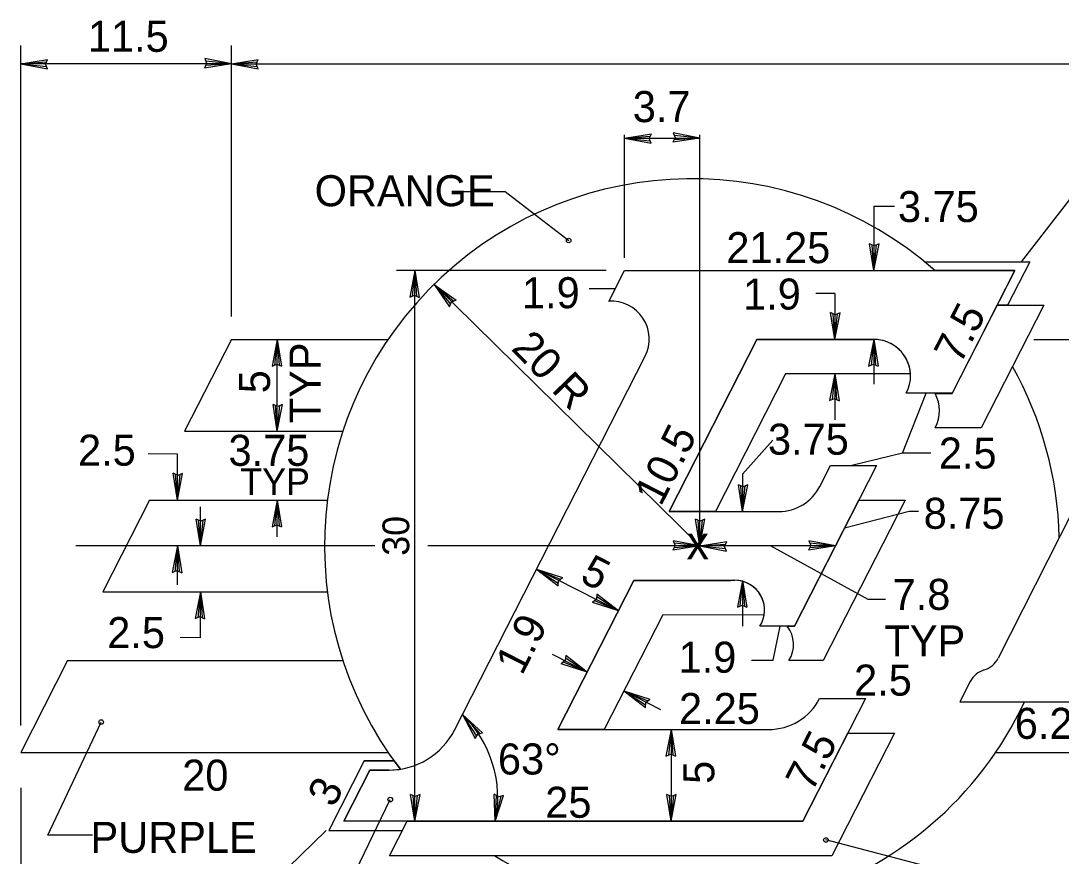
# Model space of a CAD drawing. Extents: x 10268197 to 10268739, y 2141503 to 2142677.
# Drawn here: x 10268676.64 to 10268700.09, y 2142405.46 to 2142424.3 of the extents above; entities that cross this region are included whole.
import ezdxf

# ---------------------------------------------------------------- set-up
doc = ezdxf.new("R2010")
doc.units = 0
for name, color, linetype in [('1', 7, 'Continuous'), ('21', 7, 'Continuous'), ('Default', 7, 'Continuous')]:
    doc.layers.add(name, color=color, linetype=linetype)

msp = doc.modelspace()

# ---------------------------------------------------------------- linework, layer by layer
at = {"layer": '1'}
for p, q in [((10268676.642, 2142408.409), (10268676.642, 2142423.746)), ((10268681.389, 2142417.633), (10268681.389, 2142423.746)), ((10268681.389, 2142423.333), (10268676.642, 2142423.333)), ((10268681.389, 2142423.333), (10268681.994, 2142423.429)), ((10268681.389, 2142423.333), (10268681.968, 2142423.373)), ((10268681.389, 2142423.333), (10268706.542, 2142423.333)), ((10268681.389, 2142423.333), (10268681.99, 2142423.216)), ((10268681.389, 2142423.333), (10268681.967, 2142423.272)), ((10268681.946, 2142423.323), (10268681.994, 2142423.429)), ((10268681.99, 2142423.216), (10268681.946, 2142423.323)), ((10268690.249, 2142421.657), (10268690.855, 2142421.753)), ((10268690.249, 2142418.952), (10268690.249, 2142421.73)), ((10268690.249, 2142421.657), (10268690.829, 2142421.698)), ((10268690.249, 2142421.657), (10268691.947, 2142421.657)), ((10268690.249, 2142421.657), (10268690.851, 2142421.541)), ((10268690.249, 2142421.657), (10268690.828, 2142421.597)), ((10268690.807, 2142421.647), (10268690.855, 2142421.753)), ((10268690.851, 2142421.541), (10268690.807, 2142421.647)), ((10268691.947, 2142412.457), (10268691.947, 2142421.73)), ((10268699.201, 2142418.868), (10268701.226, 2142421.486)), ((10268686.626, 2142420.448), (10268687.563, 2142420.448)), ((10268687.563, 2142420.448), (10268688.991, 2142419.346)), ((10268695.869, 2142420.118), (10268695.869, 2142418.667)), ((10268695.869, 2142420.118), (10268696.338, 2142420.118)), ((10268695.869, 2142418.667), (10268695.773, 2142419.273)), ((10268695.879, 2142419.224), (10268695.773, 2142419.273)), ((10268695.869, 2142418.667), (10268695.829, 2142419.247)), ((10268695.869, 2142418.667), (10268695.986, 2142419.269)), ((10268695.869, 2142418.667), (10268695.93, 2142419.246)), ((10268695.986, 2142419.269), (10268695.879, 2142419.224)), ((10268689.835, 2142418.667), (10268685.11, 2142418.667)), ((10268685.524, 2142418.667), (10268685.407, 2142418.066)), ((10268685.524, 2142418.667), (10268685.463, 2142418.089)), ((10268685.524, 2142406.246), (10268685.524, 2142418.667)), ((10268685.524, 2142418.667), (10268685.619, 2142418.062)), ((10268685.524, 2142418.667), (10268685.564, 2142418.088)), ((10268691.947, 2142412.457), (10268685.959, 2142418.356)), ((10268685.959, 2142418.356), (10268686.457, 2142418)), ((10268685.959, 2142418.356), (10268686.305, 2142417.851)), ((10268685.959, 2142418.356), (10268686.329, 2142417.907)), ((10268685.959, 2142418.356), (10268686.401, 2142417.979)), ((10268690.038, 2142418.253), (10268689.449, 2142418.253)), ((10268694.99, 2142418.149), (10268694.56, 2142418.149)), ((10268694.99, 2142418.149), (10268694.99, 2142417.115)), ((10268685.407, 2142418.066), (10268685.514, 2142418.11)), ((10268685.514, 2142418.11), (10268685.619, 2142418.062)), ((10268686.305, 2142417.851), (10268686.349, 2142417.959)), ((10268686.349, 2142417.959), (10268686.457, 2142418)), ((10268697.636, 2142415.898), (10268698.652, 2142417.891)), ((10268699.698, 2142417.891), (10268698.287, 2142415.124)), ((10268698.652, 2142417.891), (10268699.698, 2142417.891)), ((10268694.99, 2142417.115), (10268694.894, 2142417.72)), ((10268694.999, 2142417.672), (10268694.894, 2142417.72)), ((10268694.99, 2142417.115), (10268694.95, 2142417.695)), ((10268694.99, 2142417.115), (10268695.107, 2142417.716)), ((10268694.99, 2142417.115), (10268695.051, 2142417.693)), ((10268695.107, 2142417.716), (10268694.999, 2142417.672)), ((10268682.424, 2142417.115), (10268682.307, 2142416.513)), ((10268682.424, 2142417.115), (10268682.363, 2142416.536)), ((10268682.424, 2142415.044), (10268682.424, 2142417.115)), ((10268682.424, 2142417.115), (10268682.52, 2142416.509)), ((10268682.424, 2142417.115), (10268682.464, 2142416.535)), ((10268691.253, 2142413.233), (10268693.231, 2142417.115)), ((10268693.231, 2142417.115), (10268695.869, 2142417.115)), ((10268695.869, 2142417.115), (10268695.752, 2142416.513)), ((10268695.869, 2142417.115), (10268695.808, 2142416.536)), ((10268695.869, 2142417.115), (10268695.965, 2142416.509)), ((10268695.869, 2142417.115), (10268695.91, 2142416.535)), ((10268695.869, 2142417.115), (10268695.869, 2142416.104)), ((10268682.307, 2142416.513), (10268682.414, 2142416.557)), ((10268682.414, 2142416.557), (10268682.52, 2142416.509)), ((10268695.752, 2142416.513), (10268695.859, 2142416.557)), ((10268695.859, 2142416.557), (10268695.965, 2142416.509)), ((10268693.881, 2142416.339), (10268692.299, 2142413.233)), ((10268696.696, 2142416.339), (10268693.881, 2142416.339)), ((10268694.99, 2142416.339), (10268694.873, 2142415.737)), ((10268694.99, 2142416.339), (10268694.93, 2142415.76)), ((10268694.99, 2142416.339), (10268694.99, 2142415.304)), ((10268694.99, 2142416.339), (10268695.086, 2142415.733)), ((10268694.99, 2142416.339), (10268695.031, 2142415.759)), ((10268694.873, 2142415.737), (10268694.981, 2142415.781)), ((10268694.981, 2142415.781), (10268695.086, 2142415.733)), ((10268696.515, 2142414.546), (10268697.046, 2142415.9)), ((10268697.251, 2142415.898), (10268697.636, 2142415.898)), ((10268682.424, 2142415.044), (10268682.328, 2142415.65)), ((10268682.433, 2142415.602), (10268682.328, 2142415.65)), ((10268682.424, 2142415.044), (10268682.382, 2142415.624)), ((10268682.424, 2142415.044), (10268682.541, 2142415.646)), ((10268682.424, 2142415.044), (10268682.484, 2142415.623)), ((10268682.541, 2142415.646), (10268682.433, 2142415.602)), ((10268698.287, 2142415.124), (10268697.252, 2142415.124)), ((10268693.594, 2142414.845), (10268692.912, 2142414.075)), ((10268680.172, 2142414.527), (10268679.516, 2142414.531)), ((10268680.172, 2142413.492), (10268680.172, 2142414.527)), ((10268696.515, 2142414.546), (10268695.375, 2142414.268)), ((10268697.157, 2142414.546), (10268696.515, 2142414.546)), ((10268680.172, 2142413.492), (10268680.076, 2142414.097)), ((10268680.181, 2142414.049), (10268680.076, 2142414.097)), ((10268680.172, 2142413.492), (10268680.131, 2142414.072)), ((10268680.172, 2142413.492), (10268680.288, 2142414.093)), ((10268680.172, 2142413.492), (10268680.232, 2142414.07)), ((10268680.288, 2142414.093), (10268680.181, 2142414.049)), ((10268692.912, 2142414.075), (10268692.912, 2142413.233)), ((10268692.912, 2142413.233), (10268692.816, 2142413.838)), ((10268692.921, 2142413.79), (10268692.816, 2142413.838)), ((10268692.912, 2142413.233), (10268692.871, 2142413.813)), ((10268692.912, 2142413.233), (10268693.028, 2142413.835)), ((10268692.912, 2142413.233), (10268692.972, 2142413.811)), ((10268693.028, 2142413.835), (10268692.921, 2142413.79)), ((10268682.424, 2142413.492), (10268682.307, 2142412.89)), ((10268682.424, 2142413.492), (10268682.363, 2142412.914)), ((10268682.424, 2142412.664), (10268682.424, 2142413.492)), ((10268682.424, 2142413.492), (10268682.52, 2142412.886)), ((10268682.424, 2142413.492), (10268682.464, 2142412.912)), ((10268694.08, 2142410.645), (10268695.531, 2142413.492)), ((10268696.576, 2142413.492), (10268694.73, 2142409.869)), ((10268695.531, 2142413.492), (10268696.576, 2142413.492)), ((10268680.69, 2142412.457), (10268680.69, 2142413.336)), ((10268692.299, 2142413.233), (10268691.253, 2142413.233)), ((10268696.669, 2142413.234), (10268695.206, 2142412.854)), ((10268696.875, 2142413.234), (10268696.669, 2142413.234)), ((10268680.69, 2142412.457), (10268680.593, 2142413.062)), ((10268680.699, 2142413.014), (10268680.593, 2142413.062)), ((10268680.69, 2142412.457), (10268680.649, 2142413.036)), ((10268680.69, 2142412.457), (10268680.806, 2142413.058)), ((10268680.69, 2142412.457), (10268680.75, 2142413.035)), ((10268680.806, 2142413.058), (10268680.699, 2142413.014)), ((10268691.947, 2142412.457), (10268691.851, 2142413.062)), ((10268691.956, 2142413.014), (10268691.851, 2142413.062)), ((10268691.947, 2142412.457), (10268691.906, 2142413.036)), ((10268691.947, 2142412.457), (10268692.063, 2142413.058)), ((10268691.947, 2142412.457), (10268692.007, 2142413.035)), ((10268692.063, 2142413.058), (10268691.956, 2142413.014)), ((10268682.307, 2142412.89), (10268682.414, 2142412.935)), ((10268682.414, 2142412.935), (10268682.52, 2142412.886)), ((10268691.947, 2142412.457), (10268691.345, 2142412.574)), ((10268691.345, 2142412.574), (10268691.389, 2142412.467)), ((10268691.947, 2142412.457), (10268691.369, 2142412.517)), ((10268691.947, 2142412.457), (10268692.552, 2142412.553)), ((10268691.947, 2142412.457), (10268692.526, 2142412.497)), ((10268692.504, 2142412.447), (10268692.552, 2142412.553)), ((10268695.004, 2142412.457), (10268694.402, 2142412.574)), ((10268694.402, 2142412.574), (10268694.446, 2142412.467)), ((10268695.004, 2142412.457), (10268694.425, 2142412.517)), ((10268684.62, 2142412.457), (10268677.886, 2142412.457)), ((10268680.172, 2142412.457), (10268680.055, 2142411.855)), ((10268680.172, 2142412.457), (10268680.111, 2142411.878)), ((10268680.172, 2142411.577), (10268680.172, 2142412.457)), ((10268680.172, 2142412.457), (10268680.268, 2142411.851)), ((10268680.172, 2142412.457), (10268680.213, 2142411.877)), ((10268691.947, 2142412.457), (10268685.814, 2142412.457)), ((10268691.389, 2142412.467), (10268691.341, 2142412.361)), ((10268691.947, 2142412.457), (10268691.341, 2142412.361)), ((10268691.947, 2142412.457), (10268691.367, 2142412.416)), ((10268695.004, 2142412.457), (10268691.947, 2142412.457)), ((10268691.947, 2142412.457), (10268692.548, 2142412.34)), ((10268691.947, 2142412.457), (10268692.525, 2142412.396)), ((10268692.548, 2142412.34), (10268692.504, 2142412.447)), ((10268695.743, 2142411.252), (10268693.54, 2142412.457)), ((10268694.446, 2142412.467), (10268694.398, 2142412.361)), ((10268695.004, 2142412.457), (10268694.398, 2142412.361)), ((10268695.004, 2142412.457), (10268694.424, 2142412.416)), ((10268680.055, 2142411.855), (10268680.162, 2142411.9)), ((10268680.162, 2142411.9), (10268680.268, 2142411.851)), ((10268690.113, 2142410.993), (10268688.267, 2142411.933)), ((10268688.267, 2142411.933), (10268688.85, 2142411.744)), ((10268688.267, 2142411.933), (10268688.751, 2142411.556)), ((10268688.267, 2142411.933), (10268688.755, 2142411.617)), ((10268688.267, 2142411.933), (10268688.802, 2142411.706)), ((10268688.749, 2142408.317), (10268690.463, 2142411.68)), ((10268688.751, 2142411.556), (10268688.76, 2142411.671)), ((10268688.76, 2142411.671), (10268688.85, 2142411.744)), ((10268690.463, 2142411.68), (10268692.636, 2142411.673)), ((10268692.912, 2142411.68), (10268692.795, 2142411.079)), ((10268692.912, 2142411.68), (10268692.851, 2142411.102)), ((10268692.912, 2142411.68), (10268693.008, 2142411.075)), ((10268692.912, 2142411.68), (10268692.952, 2142411.101)), ((10268692.912, 2142411.68), (10268692.912, 2142410.645)), ((10268680.69, 2142411.422), (10268680.573, 2142410.82)), ((10268680.69, 2142411.422), (10268680.629, 2142410.843)), ((10268680.69, 2142410.387), (10268680.69, 2142411.422)), ((10268680.69, 2142411.422), (10268680.786, 2142410.816)), ((10268680.69, 2142411.422), (10268680.73, 2142410.842)), ((10268689.629, 2142411.37), (10268689.62, 2142411.254)), ((10268690.113, 2142410.993), (10268689.629, 2142411.37)), ((10268689.62, 2142411.254), (10268689.529, 2142411.182)), ((10268690.113, 2142410.993), (10268689.529, 2142411.182)), ((10268690.113, 2142410.993), (10268689.577, 2142411.219)), ((10268690.113, 2142410.993), (10268689.625, 2142411.309)), ((10268692.795, 2142411.079), (10268692.902, 2142411.123)), ((10268692.902, 2142411.123), (10268693.008, 2142411.075)), ((10268696.129, 2142411.252), (10268695.743, 2142411.252)), ((10268680.573, 2142410.82), (10268680.68, 2142410.865)), ((10268680.68, 2142410.865), (10268680.786, 2142410.816)), ((10268691.112, 2142410.903), (10268689.794, 2142408.317)), ((10268693.397, 2142410.895), (10268691.112, 2142410.903)), ((10268693.603, 2142409.882), (10268693.759, 2142410.645)), ((10268693.918, 2142410.645), (10268694.08, 2142410.645)), ((10268680.69, 2142410.387), (10268680.231, 2142410.391)), ((10268689.408, 2142409.61), (10268688.626, 2142410.008)), ((10268688.925, 2142409.987), (10268688.915, 2142409.872)), ((10268689.408, 2142409.61), (10268688.92, 2142409.926)), ((10268689.408, 2142409.61), (10268688.925, 2142409.987)), ((10268688.915, 2142409.872), (10268688.825, 2142409.799)), ((10268689.408, 2142409.61), (10268688.825, 2142409.799)), ((10268689.408, 2142409.61), (10268688.873, 2142409.837)), ((10268693.108, 2142409.882), (10268693.603, 2142409.882)), ((10268694.73, 2142409.869), (10268693.954, 2142409.869)), ((10268691.07, 2142408.762), (10268690.237, 2142409.186)), ((10268690.237, 2142409.186), (10268690.82, 2142408.997)), ((10268690.237, 2142409.186), (10268690.72, 2142408.809)), ((10268690.237, 2142409.186), (10268690.725, 2142408.87)), ((10268690.237, 2142409.186), (10268690.772, 2142408.96)), ((10268690.73, 2142408.925), (10268690.82, 2142408.997)), ((10268690.72, 2142408.809), (10268690.73, 2142408.925)), ((10268686.595, 2142408.651), (10268687.052, 2142408.242)), ((10268686.595, 2142408.651), (10268686.885, 2142408.111)), ((10268686.595, 2142408.651), (10268686.914, 2142408.164)), ((10268686.595, 2142408.651), (10268686.994, 2142408.227)), ((10268677.248, 2142405.934), (10268678.453, 2142408.484)), ((10268689.794, 2142408.317), (10268688.749, 2142408.317)), ((10268691.301, 2142408.317), (10268691.184, 2142407.715)), ((10268691.301, 2142408.317), (10268691.24, 2142407.738)), ((10268691.301, 2142408.317), (10268691.301, 2142406.246)), ((10268691.301, 2142408.317), (10268691.397, 2142407.711)), ((10268691.301, 2142408.317), (10268691.341, 2142407.737)), ((10268686.885, 2142408.111), (10268686.94, 2142408.213)), ((10268686.94, 2142408.213), (10268687.052, 2142408.242)), ((10268694.272, 2142406.246), (10268695.286, 2142408.237)), ((10268696.332, 2142408.237), (10268694.922, 2142405.469)), ((10268695.286, 2142408.237), (10268696.332, 2142408.237)), ((10268691.184, 2142407.715), (10268691.292, 2142407.759)), ((10268691.292, 2142407.759), (10268691.397, 2142407.711)), ((10268676.642, 2142406.997), (10268676.642, 2142394.918)), ((10268682.434, 2142401.477), (10268684.97, 2142406.735)), ((10268685.524, 2142406.246), (10268685.428, 2142406.851)), ((10268685.533, 2142406.803), (10268685.428, 2142406.851)), ((10268685.524, 2142406.246), (10268685.483, 2142406.826)), ((10268685.524, 2142406.246), (10268685.641, 2142406.847)), ((10268685.524, 2142406.246), (10268685.584, 2142406.824)), ((10268685.641, 2142406.847), (10268685.533, 2142406.803)), ((10268687.336, 2142406.246), (10268687.314, 2142406.859)), ((10268687.413, 2142406.798), (10268687.314, 2142406.859)), ((10268687.336, 2142406.246), (10268687.525, 2142406.829)), ((10268687.336, 2142406.246), (10268687.366, 2142406.827)), ((10268687.336, 2142406.246), (10268687.466, 2142406.813)), ((10268687.525, 2142406.829), (10268687.413, 2142406.798)), ((10268691.301, 2142406.246), (10268691.205, 2142406.851)), ((10268691.311, 2142406.803), (10268691.205, 2142406.851)), ((10268691.301, 2142406.246), (10268691.26, 2142406.826)), ((10268691.301, 2142406.246), (10268691.417, 2142406.847)), ((10268691.301, 2142406.246), (10268691.361, 2142406.824)), ((10268691.417, 2142406.847), (10268691.311, 2142406.803)), ((10268684.956, 2142405.469), (10268685.352, 2142406.246)), ((10268685.352, 2142406.246), (10268694.272, 2142406.246)), ((10268678.256, 2142405.934), (10268677.248, 2142405.934)), ((10268681.932, 2142404.492), (10268683.527, 2142406.039)), ((10268697.447, 2142405.129), (10268694.789, 2142405.824)), ((10268694.922, 2142405.469), (10268684.956, 2142405.469))]:
    msp.add_line(p, q, dxfattribs=at)
msp.add_lwpolyline([(10268697.01, 2142418.868), (10268699.382, 2142418.868), (10268698.885, 2142417.891), (10268698.652, 2142417.891), (10268699.048, 2142418.667), (10268697.246, 2142418.667)], close=True, dxfattribs=at)
for centre in [(10268688.991, 2142419.346), (10268678.453, 2142408.484), (10268684.97, 2142406.735), (10268694.789, 2142405.824)]:
    msp.add_circle(centre, 0.0518, dxfattribs=at)
for centre, radius, start, end in [((10268695.869, 2142416.287), 0.828, 3.5833, 90), ((10268696.519, 2142415.51), 0.828, 332.2089, 27.9127), ((10268692.734, 2142411.008), 0.673, 350.3502, 98.3344), ((10268693.387, 2142410.232), 0.673, 327.421, 37.9799), ((10268684.804, 2142406.783), 2.588, 348.03, 46.2026)]:
    msp.add_arc(centre, radius, start, end, dxfattribs=at)
at = {"layer": '21'}
for p, q in [((10268676.642, 2142423.333), (10268677.247, 2142423.429)), ((10268676.642, 2142423.333), (10268677.222, 2142423.373)), ((10268676.642, 2142423.333), (10268677.244, 2142423.216)), ((10268676.642, 2142423.333), (10268677.22, 2142423.272)), ((10268677.2, 2142423.323), (10268677.247, 2142423.429)), ((10268677.244, 2142423.216), (10268677.2, 2142423.323)), ((10268680.831, 2142423.343), (10268680.783, 2142423.236)), ((10268681.389, 2142423.333), (10268680.783, 2142423.236)), ((10268681.389, 2142423.333), (10268680.787, 2142423.449)), ((10268680.787, 2142423.449), (10268680.831, 2142423.343)), ((10268681.389, 2142423.333), (10268680.809, 2142423.292)), ((10268681.389, 2142423.333), (10268680.81, 2142423.393)), ((10268691.389, 2142421.666), (10268691.341, 2142421.561)), ((10268691.947, 2142421.657), (10268691.341, 2142421.561)), ((10268691.947, 2142421.657), (10268691.345, 2142421.774)), ((10268691.345, 2142421.774), (10268691.389, 2142421.666)), ((10268691.947, 2142421.657), (10268691.367, 2142421.617)), ((10268691.947, 2142421.657), (10268691.369, 2142421.718))]:
    msp.add_line(p, q, dxfattribs=at)
at = {"layer": 'Default'}
for p, q in [((10268697.01, 2142418.868), (10268699.382, 2142418.868)), ((10268699.382, 2142418.868), (10268698.885, 2142417.891)), ((10268689.896, 2142417.973), (10268690.249, 2142418.667)), ((10268690.249, 2142418.667), (10268699.048, 2142418.667)), ((10268699.048, 2142418.667), (10268697.638, 2142415.9)), ((10268697.636, 2142415.898), (10268698.652, 2142417.891)), ((10268699.698, 2142417.891), (10268698.287, 2142415.124)), ((10268698.652, 2142417.891), (10268699.698, 2142417.891)), ((10268681.389, 2142417.115), (10268680.334, 2142415.044)), ((10268681.389, 2142417.115), (10268684.922, 2142417.115)), ((10268693.231, 2142417.115), (10268691.253, 2142413.233)), ((10268691.253, 2142413.233), (10268693.231, 2142417.115)), ((10268695.869, 2142417.115), (10268693.231, 2142417.115)), ((10268693.231, 2142417.115), (10268695.869, 2142417.115)), ((10268699.479, 2142417.115), (10268729.003, 2142417.115)), ((10268686.418, 2142408.303), (10268690.713, 2142416.734)), ((10268693.881, 2142416.339), (10268692.299, 2142413.233)), ((10268696.696, 2142416.339), (10268693.881, 2142416.339)), ((10268697.638, 2142415.9), (10268696.602, 2142415.9)), ((10268697.251, 2142415.898), (10268697.636, 2142415.898)), ((10268698.287, 2142415.124), (10268697.252, 2142415.124)), ((10268680.334, 2142415.044), (10268683.903, 2142415.044)), ((10268701.234, 2142414.991), (10268698.672, 2142409.923)), ((10268695.926, 2142414.268), (10268694.08, 2142410.645)), ((10268694.651, 2142413.798), (10268694.891, 2142414.268)), ((10268694.891, 2142414.268), (10268695.926, 2142414.268)), ((10268679.543, 2142413.492), (10268678.488, 2142411.422)), ((10268679.543, 2142413.492), (10268683.553, 2142413.492)), ((10268694.08, 2142410.645), (10268695.531, 2142413.492)), ((10268696.576, 2142413.492), (10268694.73, 2142409.869)), ((10268695.531, 2142413.492), (10268696.576, 2142413.492)), ((10268691.253, 2142413.233), (10268693.73, 2142413.233)), ((10268692.299, 2142413.233), (10268691.253, 2142413.233)), ((10268690.463, 2142411.68), (10268688.749, 2142408.317)), ((10268688.749, 2142408.317), (10268690.463, 2142411.68)), ((10268692.734, 2142411.68), (10268690.463, 2142411.68)), ((10268690.463, 2142411.68), (10268692.636, 2142411.673)), ((10268678.488, 2142411.422), (10268683.553, 2142411.422)), ((10268691.112, 2142410.903), (10268689.794, 2142408.317)), ((10268693.397, 2142410.895), (10268691.112, 2142410.903)), ((10268694.08, 2142410.645), (10268693.301, 2142410.645)), ((10268693.918, 2142410.645), (10268694.08, 2142410.645)), ((10268677.697, 2142409.869), (10268676.642, 2142407.798)), ((10268677.697, 2142409.869), (10268683.903, 2142409.869)), ((10268694.73, 2142409.869), (10268693.954, 2142409.869)), ((10268698.042, 2142409.397), (10268697.81, 2142408.937)), ((10268695.682, 2142409.013), (10268694.272, 2142406.246)), ((10268694.646, 2142409.013), (10268695.682, 2142409.013)), ((10268697.81, 2142408.937), (10268700.397, 2142408.937)), ((10268688.749, 2142408.317), (10268693.498, 2142408.317)), ((10268689.794, 2142408.317), (10268688.749, 2142408.317)), ((10268694.272, 2142406.246), (10268695.286, 2142408.237)), ((10268696.332, 2142408.237), (10268694.922, 2142405.469)), ((10268695.286, 2142408.237), (10268696.332, 2142408.237)), ((10268676.642, 2142407.798), (10268684.922, 2142407.798)), ((10268684.381, 2142407.607), (10268683.583, 2142406.039)), ((10268684.381, 2142407.607), (10268685.057, 2142407.607)), ((10268698.615, 2142407.798), (10268724.257, 2142407.798)), ((10268683.921, 2142406.246), (10268684.508, 2142407.399)), ((10268684.508, 2142407.399), (10268683.922, 2142406.246)), ((10268684.943, 2142407.4), (10268684.508, 2142407.399)), ((10268684.508, 2142407.399), (10268684.943, 2142407.399)), ((10268694.272, 2142406.246), (10268683.921, 2142406.246)), ((10268684.956, 2142405.469), (10268685.352, 2142406.246)), ((10268685.352, 2142406.246), (10268694.272, 2142406.246)), ((10268683.583, 2142406.039), (10268685.246, 2142406.039)), ((10268694.922, 2142405.469), (10268684.956, 2142405.469))]:
    msp.add_line(p, q, dxfattribs=at)
msp.add_lwpolyline([(10268685.057, 2142407.607), (10268684.381, 2142407.607), (10268683.583, 2142406.039), (10268685.246, 2142406.039), (10268685.352, 2142406.246), (10268683.921, 2142406.246), (10268684.508, 2142407.399), (10268684.943, 2142407.399), (10268685.197, 2142407.419)], close=True, dxfattribs=at)
for centre, radius, start, end in [((10268691.769, 2142412.457), 8.281, 48.5904, 217.4725), ((10268689.953, 2142417.122), 0.854, 332.9998, 93.8045), ((10268695.869, 2142416.287), 0.828, 332.2089, 90), ((10268695.869, 2142416.287), 0.828, 3.5833, 90), ((10268691.769, 2142412.457), 8.281, 1.2967, 29.2778), ((10268696.519, 2142415.51), 0.828, 332.2089, 27.9127), ((10268693.729, 2142414.268), 1.035, 270, 332.9883), ((10268692.734, 2142411.008), 0.673, 350.3502, 98.3344), ((10268692.734, 2142411.008), 0.673, 327.421, 90), ((10268693.387, 2142410.232), 0.673, 327.421, 37.9799), ((10268693.498, 2142409.61), 1.294, 270, 332.5096), ((10268691.769, 2142412.457), 8.281, 237.5383, 334.8493), ((10268684.943, 2142409.056), 1.656, 270, 332.9991)]:
    msp.add_arc(centre, radius, start, end, dxfattribs=at)
for centre, start_param, end_param in [((10268698.211, 2142410.161), 0.286787, 1.099486), ((10268698.504, 2142409.161), 3.428379, 4.240701)]:
    msp.add_ellipse(centre, major_axis=(0, -0.521), ratio=0.992614, start_param=start_param, end_param=end_param, dxfattribs=at)

# ---------------------------------------------------------------- texts
at = {"layer": '1'}
for s, height, p in [('11.5', 0.7, (10268678.154, 2142423.602)), ('3.7', 0.7, (10268690.436, 2142422.016)), ('ORANGE', 0.7, (10268683.265, 2142420.119)), ('3.75', 0.7, (10268696.413, 2142419.762)), ('21.25', 0.7, (10268692.545, 2142418.835)), ('1.9', 0.7, (10268687.938, 2142417.818)), ('1.9', 0.7, (10268692.922, 2142417.788)), ('3.75', 0.7, (10268693.483, 2142414.514)), ('2.5', 0.7, (10268677.932, 2142414.267)), ('3.75', 0.7, (10268681.324, 2142414.263)), ('2.5', 0.7, (10268697.334, 2142414.202)), ('TYP', 0.6037, (10268681.589, 2142413.602)), ('8.75', 0.7, (10268696.993, 2142412.843)), ('x', 0.755, (10268691.648, 2142412.156)), ('7.8', 0.7, (10268696.293, 2142411.014)), ('2.5', 0.7, (10268678.59, 2142410.152)), ('TYP', 0.7, (10268696.108, 2142409.964)), ('1.9', 0.7, (10268691.469, 2142409.597)), ('2.5', 0.7, (10268695.424, 2142409.08)), ('2.25', 0.7, (10268691.478, 2142408.44)), ('6.25', 0.7, (10268699.046, 2142408.105)), ('63°', 0.7, (10268687.396, 2142407.301)), ('20', 0.7, (10268680.28, 2142406.936)), ('25', 0.7, (10268688.463, 2142406.325)), ('PURPLE', 0.7, (10268678.214, 2142405.533))]:
    msp.add_text(s, height=height, dxfattribs=at).set_placement(p)
for s, height, rotation, p in [('7.5', 0.7, 63, (10268697.82, 2142416.53)), ('20 R', 0.7, 314.1812, (10268687.673, 2142416.895)), ('TYP', 0.7, 90, (10268683.399, 2142415.225)), ('5', 0.7, 90, (10268682.258, 2142415.9)), ('10.5', 0.7, 63.0402, (10268691.069, 2142413.329)), ('30', 0.6037, 90, (10268685.397, 2142412.235)), ('5', 0.7, 332.9866, (10268689.216, 2142411.666)), ('1.9', 0.7, 63.0402, (10268687.939, 2142409.516)), ('7.5', 0.7, 63, (10268694.474, 2142406.88)), ('5', 0.7, 90, (10268692.273, 2142407.089)), ('3', 0.7, 63, (10268683.697, 2142406.532))]:
    msp.add_text(s, height=height, rotation=rotation, dxfattribs=at).set_placement(p)

doc.saveas('drawing.dxf')
